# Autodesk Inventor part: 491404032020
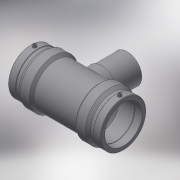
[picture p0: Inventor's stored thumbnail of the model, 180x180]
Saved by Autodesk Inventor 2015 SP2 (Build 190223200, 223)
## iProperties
Created: 2017-06
Part Number: 491404032020
Material: Generic
Description: PLASSON REDUCING TEE 32x20x32
Document SubType Name: Modeling
Designer: KIM
Mass: 81.8042 g
Surface Area: 341.927 cm^2
Volume: 81.8042 cm^3
Density: 1 g/cm^3
Appearance: Default
Author: KIM
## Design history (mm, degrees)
derived "491404.ipt"
feature "Solid1::491404.ipt"
tag "TaggingFeature1"
body "Solid1"
other parameters: "d0" = 104, "d1" = 32, "d2" = 44, "d3" = 39, "d4" = 20.8, "d5" = 39.6, "d6" = 30.4, "d7" = 32, "d8" = 168 deg, "d10" = 15.6, "d11" = 5.2, "d13" = 104, "d14" = 17.6296, "d17" = 28.8, "d18" = 32, "d19" = 3.52592, "d20" = 168 deg, "d22" = 40.92, "d23" = 44, "d25" = 135 deg, "d26" = 72.8, "d29" = 43, "d30" = 15, "d31" = 41.6, "d34" = 5 deg, "d35" = 15, "d39" = 5 deg, "d41" = 4, "d42" = 14, "d43" = 0, "d45" = 4, "d46" = 6, "d47" = 0, "d48" = -66, "d51" = 0, "d52" = 16, "d54" = 0, "d55" = 39.6, "d56" = 44, "d57" = 36.4, "d58" = 135 deg, "d59" = 39, "d60" = 39, "d61" = 135 deg, "d62" = 66, "d72" = 47.32, "d73" = 23.66, "d74" = -66, "d75" = 21, "d77" = 0, "d78" = 16, "d80" = 0, "d82" = 44, "d83" = 0, "d84" = 3, "d85" = 0, "d86" = 13, "d87" = 40.1016, "d88" = 5.2, "d89" = 3, "d90" = 0, "d_" = 32, "L_" = 104, "L_1" = 39, "D_" = 44, "A_" = 43, "d_2" = 12, "H_" = 66
